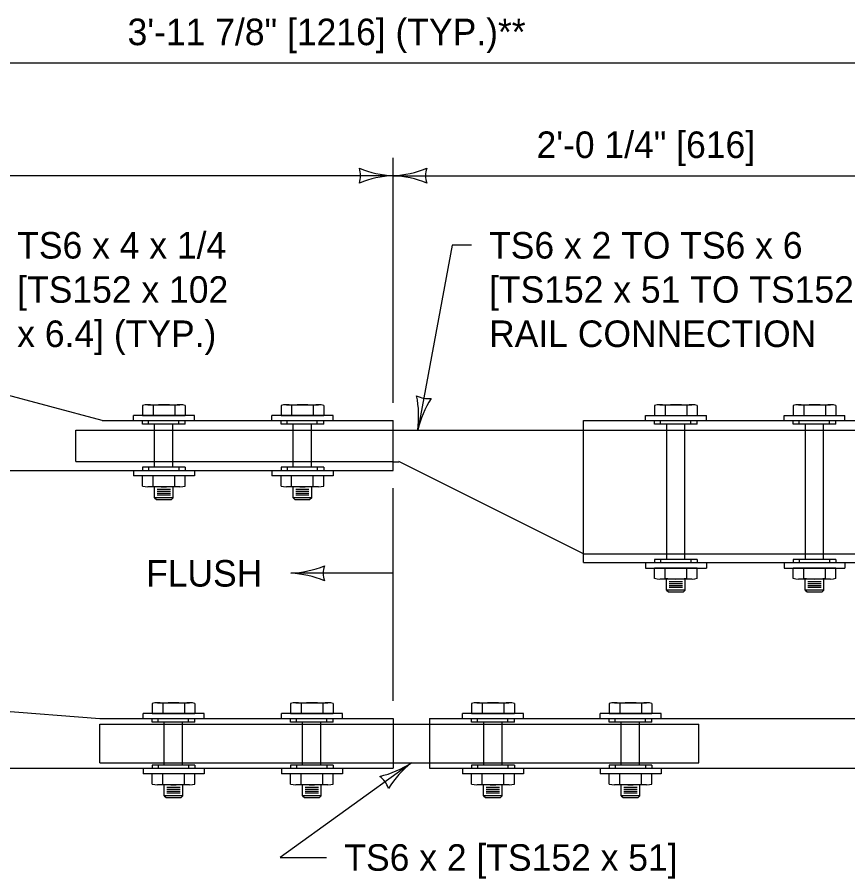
# Model space of a CAD drawing. Extents: x 49991.4 to 50021, y 49987.6 to 50011.4.
# Drawn here: x 50006.762 to 50008.64, y 49992.975 to 49994.923 of the extents above; entities that cross this region are included whole.
import ezdxf

# ---------------------------------------------------------------- set-up
doc = ezdxf.new("R2010")
doc.units = 0
for name, color, linetype in [('Level 1', 7, 'Continuous'), ('Level 2', 7, 'Continuous'), ('Level 3', 7, 'Continuous'), ('Level 4', 7, 'Continuous')]:
    doc.layers.add(name, color=color, linetype=linetype)

msp = doc.modelspace()

# ---------------------------------------------------------------- linework, layer by layer
at = {"layer": 'Level 1'}
for p, q in [((50006.954, 49994.0107), (50006.608, 49994.1035)), ((50007.0451, 49994.0451), (50007.0451, 49994.022)), ((50007.0572, 49994.0466), (50007.1295, 49994.0466)), ((50007.069, 49994.0451), (50007.069, 49994.0221)), ((50007.1178, 49994.0451), (50007.1178, 49994.0221)), ((50007.1417, 49994.0451), (50007.1417, 49994.022)), ((50007.3583, 49994.0451), (50007.3583, 49994.022)), ((50007.3704, 49994.0466), (50007.4427, 49994.0466)), ((50007.3822, 49994.0451), (50007.3822, 49994.0221)), ((50007.431, 49994.0451), (50007.431, 49994.0221)), ((50007.4549, 49994.0451), (50007.4549, 49994.022)), ((50008.2031, 49994.0453), (50008.2031, 49994.0222)), ((50008.2152, 49994.0468), (50008.2875, 49994.0468)), ((50008.227, 49994.0453), (50008.227, 49994.0223)), ((50008.2758, 49994.0453), (50008.2758, 49994.0223)), ((50008.2997, 49994.0453), (50008.2997, 49994.0222)), ((50008.5167, 49994.0453), (50008.5167, 49994.0222)), ((50008.5288, 49994.0468), (50008.6011, 49994.0468)), ((50008.5406, 49994.0453), (50008.5406, 49994.0223)), ((50008.5894, 49994.0453), (50008.5894, 49994.0223)), ((50008.6133, 49994.0453), (50008.6133, 49994.0222)), ((50007.1627, 49994.022), (50007.0244, 49994.022)), ((50007.0244, 49994.0107), (50007.0244, 49994.022)), ((50007.0451, 49994.022), (50007.1417, 49994.022)), ((50007.1627, 49994.0107), (50007.1627, 49994.022)), ((50007.4759, 49994.022), (50007.3376, 49994.022)), ((50007.3376, 49994.0107), (50007.3376, 49994.022)), ((50007.3583, 49994.022), (50007.4549, 49994.022)), ((50007.4759, 49994.0107), (50007.4759, 49994.022)), ((50008.1824, 49994.0222), (50008.3206, 49994.0222)), ((50008.1824, 49994.0107), (50008.1824, 49994.0222)), ((50008.2031, 49994.0222), (50008.2997, 49994.0222)), ((50008.3206, 49994.0107), (50008.3206, 49994.0222)), ((50008.496, 49994.0222), (50008.6336, 49994.0222)), ((50008.496, 49994.0107), (50008.496, 49994.0222)), ((50008.5158, 49994.0222), (50008.6234, 49994.0222)), ((50008.5167, 49994.0222), (50008.6133, 49994.0222)), ((50008.6336, 49994.0107), (50008.6336, 49994.0222)), ((50006.954, 49994.0107), (50007.6117, 49994.0107)), ((50007.6117, 49993.898), (50007.6117, 49994.0107)), ((50008.0426, 49994.0107), (50009.1126, 49994.0107)), ((50008.0426, 49993.6898), (50008.0426, 49994.0107)), ((50007.6117, 49993.9892), (50008.0426, 49993.9892)), ((50007.6116, 49993.9179), (50007.625, 49993.9179)), ((50008.0426, 49993.7095), (50007.6249, 49993.9181)), ((50006.7232, 49993.898), (50007.6117, 49993.898)), ((50007.0244, 49993.898), (50007.0244, 49993.8858)), ((50007.1627, 49993.8858), (50007.0244, 49993.8858)), ((50007.1417, 49993.8858), (50007.0451, 49993.8858)), ((50007.0451, 49993.8627), (50007.0451, 49993.8858)), ((50007.069, 49993.8627), (50007.069, 49993.8857)), ((50007.1178, 49993.8627), (50007.1178, 49993.8857)), ((50007.1417, 49993.8627), (50007.1417, 49993.8858)), ((50007.1627, 49993.898), (50007.1627, 49993.8858)), ((50007.3376, 49993.898), (50007.3376, 49993.8858)), ((50007.4759, 49993.8858), (50007.3376, 49993.8858)), ((50007.4549, 49993.8858), (50007.3583, 49993.8858)), ((50007.3583, 49993.8627), (50007.3583, 49993.8858)), ((50007.3822, 49993.8627), (50007.3822, 49993.8857)), ((50007.431, 49993.8627), (50007.431, 49993.8857)), ((50007.4549, 49993.8627), (50007.4549, 49993.8858)), ((50007.4759, 49993.898), (50007.4759, 49993.8858)), ((50007.1296, 49993.8612), (50007.0573, 49993.8612)), ((50007.0722, 49993.8363), (50007.0722, 49993.8613)), ((50007.0783, 49993.8554), (50007.108, 49993.8554)), ((50007.0783, 49993.8512), (50007.108, 49993.8512)), ((50007.0783, 49993.8469), (50007.108, 49993.8469)), ((50007.1144, 49993.8363), (50007.1144, 49993.8613)), ((50007.4428, 49993.8612), (50007.3705, 49993.8612)), ((50007.3854, 49993.8363), (50007.3854, 49993.8613)), ((50007.3915, 49993.8554), (50007.4212, 49993.8554)), ((50007.3915, 49993.8512), (50007.4212, 49993.8512)), ((50007.3915, 49993.8469), (50007.4212, 49993.8469)), ((50007.4276, 49993.8363), (50007.4276, 49993.8613)), ((50007.1144, 49993.8363), (50007.0722, 49993.8363)), ((50007.0722, 49993.8363), (50007.0764, 49993.8321)), ((50007.0764, 49993.8321), (50007.1102, 49993.8321)), ((50007.0783, 49993.8427), (50007.108, 49993.8427)), ((50007.1144, 49993.8363), (50007.1102, 49993.8321)), ((50007.4276, 49993.8363), (50007.3854, 49993.8363)), ((50007.3854, 49993.8363), (50007.3896, 49993.8321)), ((50007.3896, 49993.8321), (50007.4234, 49993.8321)), ((50007.3915, 49993.8427), (50007.4212, 49993.8427)), ((50007.4276, 49993.8363), (50007.4234, 49993.8321)), ((50008.0426, 49993.6898), (50009.0361, 49993.6898)), ((50008.1824, 49993.6898), (50008.1824, 49993.6772)), ((50008.3206, 49993.6898), (50008.3206, 49993.6772)), ((50008.496, 49993.6898), (50008.496, 49993.6772)), ((50008.6336, 49993.6898), (50008.6336, 49993.6772)), ((50008.1824, 49993.6772), (50008.3206, 49993.6772)), ((50008.2997, 49993.6772), (50008.2031, 49993.6772)), ((50008.2031, 49993.6541), (50008.2031, 49993.6772)), ((50008.227, 49993.6541), (50008.227, 49993.6771)), ((50008.2758, 49993.6541), (50008.2758, 49993.6771)), ((50008.2997, 49993.6541), (50008.2997, 49993.6772)), ((50008.496, 49993.6772), (50008.6336, 49993.6772)), ((50008.5158, 49993.6772), (50008.6234, 49993.6772)), ((50008.6133, 49993.6772), (50008.5167, 49993.6772)), ((50008.5167, 49993.6541), (50008.5167, 49993.6772)), ((50008.5406, 49993.6541), (50008.5406, 49993.6771)), ((50008.5894, 49993.6541), (50008.5894, 49993.6771)), ((50008.6133, 49993.6541), (50008.6133, 49993.6772)), ((50008.2876, 49993.6526), (50008.2153, 49993.6526)), ((50008.2302, 49993.6277), (50008.2302, 49993.6527)), ((50008.2724, 49993.6277), (50008.2724, 49993.6527)), ((50008.6012, 49993.6526), (50008.5289, 49993.6526)), ((50008.5438, 49993.6277), (50008.5438, 49993.6527)), ((50008.586, 49993.6277), (50008.586, 49993.6527)), ((50008.2363, 49993.6468), (50008.266, 49993.6468)), ((50008.2363, 49993.6426), (50008.266, 49993.6426)), ((50008.2363, 49993.6383), (50008.266, 49993.6383)), ((50008.2363, 49993.6341), (50008.266, 49993.6341)), ((50008.5499, 49993.6468), (50008.5796, 49993.6468)), ((50008.5499, 49993.6426), (50008.5796, 49993.6426)), ((50008.5499, 49993.6383), (50008.5796, 49993.6383)), ((50008.5499, 49993.6341), (50008.5796, 49993.6341)), ((50008.2724, 49993.6277), (50008.2302, 49993.6277)), ((50008.2302, 49993.6277), (50008.2344, 49993.6235)), ((50008.2344, 49993.6235), (50008.2682, 49993.6235)), ((50008.2724, 49993.6277), (50008.2682, 49993.6235)), ((50008.586, 49993.6277), (50008.5438, 49993.6277)), ((50008.5438, 49993.6277), (50008.548, 49993.6235)), ((50008.548, 49993.6235), (50008.5818, 49993.6235)), ((50008.586, 49993.6277), (50008.5818, 49993.6235)), ((50006.5485, 49993.3681), (50006.9485, 49993.3369)), ((50007.0669, 49993.3713), (50007.0669, 49993.3482)), ((50007.079, 49993.3728), (50007.1513, 49993.3728)), ((50007.0908, 49993.3713), (50007.0908, 49993.3483)), ((50007.1396, 49993.3713), (50007.1396, 49993.3483)), ((50007.1635, 49993.3713), (50007.1635, 49993.3482)), ((50007.3798, 49993.3713), (50007.3798, 49993.3482)), ((50007.3919, 49993.3728), (50007.4642, 49993.3728)), ((50007.4037, 49993.3713), (50007.4037, 49993.3483)), ((50007.4525, 49993.3713), (50007.4525, 49993.3483)), ((50007.4764, 49993.3713), (50007.4764, 49993.3482)), ((50007.7893, 49993.3713), (50007.7893, 49993.3482)), ((50007.8014, 49993.3728), (50007.8737, 49993.3728)), ((50007.8132, 49993.3713), (50007.8132, 49993.3483)), ((50007.862, 49993.3713), (50007.862, 49993.3483)), ((50007.8859, 49993.3713), (50007.8859, 49993.3482)), ((50008.1005, 49993.3713), (50008.1005, 49993.3482)), ((50008.1126, 49993.3728), (50008.1849, 49993.3728)), ((50008.1244, 49993.3713), (50008.1244, 49993.3483)), ((50008.1732, 49993.3713), (50008.1732, 49993.3483)), ((50008.1971, 49993.3713), (50008.1971, 49993.3482)), ((50007.1845, 49993.3482), (50007.0462, 49993.3482)), ((50007.0462, 49993.3369), (50007.0462, 49993.3482)), ((50007.0669, 49993.3482), (50007.1635, 49993.3482)), ((50007.1845, 49993.3369), (50007.1845, 49993.3482)), ((50007.4974, 49993.3482), (50007.3591, 49993.3482)), ((50007.3591, 49993.3369), (50007.3591, 49993.3482)), ((50007.3798, 49993.3482), (50007.4764, 49993.3482)), ((50007.4974, 49993.3369), (50007.4974, 49993.3482)), ((50007.9069, 49993.3482), (50007.7686, 49993.3482)), ((50007.7686, 49993.3369), (50007.7686, 49993.3482)), ((50007.7893, 49993.3482), (50007.8859, 49993.3482)), ((50007.9069, 49993.3369), (50007.9069, 49993.3482)), ((50008.2181, 49993.3482), (50008.0798, 49993.3482)), ((50008.0798, 49993.3369), (50008.0798, 49993.3482)), ((50008.1005, 49993.3482), (50008.1971, 49993.3482)), ((50008.2181, 49993.3369), (50008.2181, 49993.3482)), ((50006.9485, 49993.3369), (50007.6118, 49993.3369)), ((50007.6118, 49993.3369), (50007.6118, 49993.2246)), ((50007.6118, 49993.3244), (50007.6939, 49993.3244)), ((50007.6939, 49993.3369), (50008.7782, 49993.3369)), ((50007.6939, 49993.3369), (50007.6939, 49993.2246)), ((50005.3414, 49993.2246), (50007.6118, 49993.2246)), ((50007.0462, 49993.2246), (50007.0462, 49993.212)), ((50007.1845, 49993.2246), (50007.1845, 49993.212)), ((50007.3591, 49993.2246), (50007.3591, 49993.212)), ((50007.4974, 49993.2246), (50007.4974, 49993.212)), ((50007.6118, 49993.2372), (50007.6939, 49993.2372)), ((50007.6939, 49993.2246), (50008.7782, 49993.2246)), ((50007.7686, 49993.2246), (50007.7686, 49993.212)), ((50007.9069, 49993.2246), (50007.9069, 49993.212)), ((50008.0798, 49993.2246), (50008.0798, 49993.212)), ((50008.2181, 49993.2246), (50008.2181, 49993.212)), ((50007.1845, 49993.212), (50007.0462, 49993.212)), ((50007.1635, 49993.212), (50007.0669, 49993.212)), ((50007.0669, 49993.1889), (50007.0669, 49993.212)), ((50007.0908, 49993.1889), (50007.0908, 49993.2119)), ((50007.1396, 49993.1889), (50007.1396, 49993.2119)), ((50007.1635, 49993.1889), (50007.1635, 49993.212)), ((50007.4974, 49993.212), (50007.3591, 49993.212)), ((50007.4764, 49993.212), (50007.3798, 49993.212)), ((50007.3798, 49993.1889), (50007.3798, 49993.212)), ((50007.4037, 49993.1889), (50007.4037, 49993.2119)), ((50007.4525, 49993.1889), (50007.4525, 49993.2119)), ((50007.4764, 49993.1889), (50007.4764, 49993.212)), ((50007.9069, 49993.212), (50007.7686, 49993.212)), ((50007.8859, 49993.212), (50007.7893, 49993.212)), ((50007.7893, 49993.1889), (50007.7893, 49993.212)), ((50007.8132, 49993.1889), (50007.8132, 49993.2119)), ((50007.862, 49993.1889), (50007.862, 49993.2119)), ((50007.8859, 49993.1889), (50007.8859, 49993.212)), ((50008.2181, 49993.212), (50008.0798, 49993.212)), ((50008.1971, 49993.212), (50008.1005, 49993.212)), ((50008.1005, 49993.1889), (50008.1005, 49993.212)), ((50008.1244, 49993.1889), (50008.1244, 49993.2119)), ((50008.1732, 49993.1889), (50008.1732, 49993.2119)), ((50008.1971, 49993.1889), (50008.1971, 49993.212)), ((50007.1514, 49993.1874), (50007.0791, 49993.1874)), ((50007.094, 49993.1625), (50007.094, 49993.1875)), ((50007.1362, 49993.1625), (50007.1362, 49993.1875)), ((50007.4643, 49993.1874), (50007.392, 49993.1874)), ((50007.4069, 49993.1625), (50007.4069, 49993.1875)), ((50007.4491, 49993.1625), (50007.4491, 49993.1875)), ((50007.8738, 49993.1874), (50007.8015, 49993.1874)), ((50007.8164, 49993.1625), (50007.8164, 49993.1875)), ((50007.8586, 49993.1625), (50007.8586, 49993.1875)), ((50008.185, 49993.1874), (50008.1127, 49993.1874)), ((50008.1276, 49993.1625), (50008.1276, 49993.1875)), ((50008.1698, 49993.1625), (50008.1698, 49993.1875)), ((50007.1001, 49993.1816), (50007.1298, 49993.1816)), ((50007.1001, 49993.1774), (50007.1298, 49993.1774)), ((50007.1001, 49993.1731), (50007.1298, 49993.1731)), ((50007.1001, 49993.1689), (50007.1298, 49993.1689)), ((50007.413, 49993.1816), (50007.4427, 49993.1816)), ((50007.413, 49993.1774), (50007.4427, 49993.1774)), ((50007.413, 49993.1731), (50007.4427, 49993.1731)), ((50007.413, 49993.1689), (50007.4427, 49993.1689)), ((50007.8225, 49993.1816), (50007.8522, 49993.1816)), ((50007.8225, 49993.1774), (50007.8522, 49993.1774)), ((50007.8225, 49993.1731), (50007.8522, 49993.1731)), ((50007.8225, 49993.1689), (50007.8522, 49993.1689)), ((50008.1337, 49993.1816), (50008.1634, 49993.1816)), ((50008.1337, 49993.1774), (50008.1634, 49993.1774)), ((50008.1337, 49993.1731), (50008.1634, 49993.1731)), ((50008.1337, 49993.1689), (50008.1634, 49993.1689)), ((50007.1362, 49993.1625), (50007.094, 49993.1625)), ((50007.094, 49993.1625), (50007.0982, 49993.1583)), ((50007.0982, 49993.1583), (50007.132, 49993.1583)), ((50007.1362, 49993.1625), (50007.132, 49993.1583)), ((50007.4491, 49993.1625), (50007.4069, 49993.1625)), ((50007.4069, 49993.1625), (50007.4111, 49993.1583)), ((50007.4111, 49993.1583), (50007.4449, 49993.1583)), ((50007.4491, 49993.1625), (50007.4449, 49993.1583)), ((50007.8586, 49993.1625), (50007.8164, 49993.1625)), ((50007.8164, 49993.1625), (50007.8206, 49993.1583)), ((50007.8206, 49993.1583), (50007.8544, 49993.1583)), ((50007.8586, 49993.1625), (50007.8544, 49993.1583)), ((50008.1698, 49993.1625), (50008.1276, 49993.1625)), ((50008.1276, 49993.1625), (50008.1318, 49993.1583)), ((50008.1318, 49993.1583), (50008.1656, 49993.1583)), ((50008.1698, 49993.1625), (50008.1656, 49993.1583))]:
    msp.add_line(p, q, dxfattribs=at)
for centre, major_axis, start_param, end_param in [((50007.0572, 49994.0349), (0.0242, 0), 1.056847, 2.094396), ((50007.0934, 49993.9999), (0.0966, 0), 1.315951, 1.825641), ((50007.1296, 49994.0349), (0.0242, 0), 1.047198, 2.084746), ((50007.3704, 49994.0349), (0.0242, 0), 1.056847, 2.094396), ((50007.4066, 49993.9999), (0.0966, 0), 1.315951, 1.825641), ((50007.4428, 49994.0349), (0.0242, 0), 1.047198, 2.084746), ((50008.2152, 49994.0351), (0.0242, 0), 1.056847, 2.094396), ((50008.2514, 49994.0001), (0.0966, 0), 1.315951, 1.825641), ((50008.2876, 49994.0351), (0.0242, 0), 1.047198, 2.084746), ((50008.5288, 49994.0351), (0.0242, 0), 1.056847, 2.094396), ((50008.565, 49994.0001), (0.0966, 0), 1.315951, 1.825641), ((50008.6012, 49994.0351), (0.0242, 0), 1.047198, 2.084746), ((50007.0572, 49993.8729), (-0.0242, 0), 1.047198, 2.084746), ((50007.0934, 49993.9079), (-0.0966, 0), 1.315951, 1.825641), ((50007.1296, 49993.8729), (-0.0242, 0), 1.056847, 2.094396), ((50007.3704, 49993.8729), (-0.0242, 0), 1.047198, 2.084746), ((50007.4066, 49993.9079), (-0.0966, 0), 1.315951, 1.825641), ((50007.4428, 49993.8729), (-0.0242, 0), 1.056847, 2.094396), ((50008.2152, 49993.6643), (-0.0242, 0), 1.047198, 2.084746), ((50008.2514, 49993.6993), (-0.0966, 0), 1.315951, 1.825641), ((50008.2876, 49993.6643), (-0.0242, 0), 1.056847, 2.094396), ((50008.5288, 49993.6643), (-0.0242, 0), 1.047198, 2.084746), ((50008.565, 49993.6993), (-0.0966, 0), 1.315951, 1.825641), ((50008.6012, 49993.6643), (-0.0242, 0), 1.056847, 2.094396), ((50007.079, 49993.3611), (0.0242, 0), 1.056847, 2.094396), ((50007.1152, 49993.3261), (0.0966, 0), 1.315951, 1.825641), ((50007.1514, 49993.3611), (0.0242, 0), 1.047198, 2.084746), ((50007.3919, 49993.3611), (0.0242, 0), 1.056847, 2.094396), ((50007.4281, 49993.3261), (0.0966, 0), 1.315951, 1.825641), ((50007.4643, 49993.3611), (0.0242, 0), 1.047198, 2.084746), ((50007.8014, 49993.3611), (0.0242, 0), 1.056847, 2.094396), ((50007.8376, 49993.3261), (0.0966, 0), 1.315951, 1.825641), ((50007.8738, 49993.3611), (0.0242, 0), 1.047198, 2.084746), ((50008.1126, 49993.3611), (0.0242, 0), 1.056847, 2.094396), ((50008.1488, 49993.3261), (0.0966, 0), 1.315951, 1.825641), ((50008.185, 49993.3611), (0.0242, 0), 1.047198, 2.084746), ((50007.079, 49993.1991), (-0.0242, 0), 1.047198, 2.084746), ((50007.1152, 49993.2341), (-0.0966, 0), 1.315951, 1.825641), ((50007.1514, 49993.1991), (-0.0242, 0), 1.056847, 2.094396), ((50007.3919, 49993.1991), (-0.0242, 0), 1.047198, 2.084746), ((50007.4281, 49993.2341), (-0.0966, 0), 1.315951, 1.825641), ((50007.4643, 49993.1991), (-0.0242, 0), 1.056847, 2.094396), ((50007.8014, 49993.1991), (-0.0242, 0), 1.047198, 2.084746), ((50007.8376, 49993.2341), (-0.0966, 0), 1.315951, 1.825641), ((50007.8738, 49993.1991), (-0.0242, 0), 1.056847, 2.094396), ((50008.1126, 49993.1991), (-0.0242, 0), 1.047198, 2.084746), ((50008.1488, 49993.2341), (-0.0966, 0), 1.315951, 1.825641), ((50008.185, 49993.1991), (-0.0242, 0), 1.056847, 2.094396)]:
    msp.add_ellipse(centre, major_axis=major_axis, ratio=0.483301, start_param=start_param, end_param=end_param, dxfattribs=at)
at = {"layer": 'Level 3'}
for p, q in [((50006.3999, 49994.8197), (50008.9351, 49994.8197)), ((50007.6116, 49994.0507), (50007.6116, 49994.6046)), ((50007.6116, 49994.5646), (50005.3414, 49994.5646)), ((50007.6116, 49994.5646), (50008.9351, 49994.5646)), ((50007.7454, 49994.4072), (50007.6674, 49993.9892)), ((50007.7887, 49994.4072), (50007.7454, 49994.4072)), ((50007.6119, 49993.3769), (50007.6119, 49993.858)), ((50007.6119, 49993.6655), (50007.3802, 49993.6655)), ((50007.653, 49993.2372), (50007.356, 49993.0229)), ((50007.356, 49993.0229), (50007.4614, 49993.0229))]:
    msp.add_line(p, q, dxfattribs=at)
for centre, radius, start, end in [((50007.6208, 49994.7867), 0.2223, 247.456, 267.6395), ((50007.4834, 49994.5646), 0.0548, 342.1388, 17.8612), ((50007.6001, 49994.7973), 0.233, 272.8273, 292.0772), ((50007.7398, 49994.5646), 0.0548, 162.1388, 197.8612), ((50007.6231, 49994.3319), 0.233, 92.8273, 112.0772), ((50007.6025, 49994.3425), 0.2223, 67.456, 87.6395), ((50007.6909, 49994.1152), 0.0548, 241.5671, 277.2895), ((50007.4365, 49994.0206), 0.233, 352.2556, 11.5055), ((50007.8841, 49993.9394), 0.2223, 146.8843, 167.0678), ((50007.3687, 49993.8983), 0.233, 272.8273, 292.0772), ((50007.5084, 49993.6655), 0.0548, 162.1388, 197.8612), ((50007.3711, 49993.4434), 0.2223, 67.456, 87.6395), ((50007.5305, 49993.4227), 0.2223, 283.2637, 303.4472), ((50007.7985, 49993.0552), 0.233, 128.635, 147.8848), ((50007.549, 49993.1622), 0.0548, 17.9465, 53.6688)]:
    msp.add_arc(centre, radius, start, end, dxfattribs=at)
at = {"layer": 'Level 4'}
for p, q in [((50007.0451, 49994.0028), (50007.0451, 49994.0107)), ((50007.1417, 49994.0028), (50007.0451, 49994.0028)), ((50007.0587, 49994.0028), (50007.0587, 49994.0107)), ((50007.0724, 49993.9056), (50007.0724, 49994.0028)), ((50007.1138, 49993.9056), (50007.1138, 49994.0028)), ((50007.1271, 49994.0028), (50007.1271, 49994.0107)), ((50007.1417, 49994.0028), (50007.1417, 49994.0107)), ((50007.3583, 49994.0028), (50007.3583, 49994.0107)), ((50007.4549, 49994.0028), (50007.3583, 49994.0028)), ((50007.3719, 49994.0028), (50007.3719, 49994.0107)), ((50007.3856, 49993.9056), (50007.3856, 49994.0028)), ((50007.427, 49993.9056), (50007.427, 49994.0028)), ((50007.4403, 49994.0028), (50007.4403, 49994.0107)), ((50007.4549, 49994.0028), (50007.4549, 49994.0107)), ((50008.2031, 49994.003), (50008.2031, 49994.0107)), ((50008.2997, 49994.003), (50008.2031, 49994.003)), ((50008.2167, 49994.003), (50008.2167, 49994.0107)), ((50008.2304, 49993.697), (50008.2304, 49994.003)), ((50008.2718, 49993.697), (50008.2718, 49994.003)), ((50008.2851, 49994.003), (50008.2851, 49994.0107)), ((50008.2997, 49994.003), (50008.2997, 49994.0107)), ((50008.5167, 49994.003), (50008.5167, 49994.0107)), ((50008.6133, 49994.003), (50008.5167, 49994.003)), ((50008.5303, 49994.003), (50008.5303, 49994.0107)), ((50008.544, 49993.697), (50008.544, 49994.003)), ((50008.5854, 49993.697), (50008.5854, 49994.003)), ((50008.5987, 49994.003), (50008.5987, 49994.0107)), ((50008.6133, 49994.003), (50008.6133, 49994.0107)), ((50006.8942, 49993.9892), (50007.6117, 49993.9892)), ((50006.8942, 49993.9181), (50006.8942, 49993.9892)), ((50008.0426, 49993.9892), (50008.7737, 49993.9892)), ((50006.8942, 49993.9181), (50007.6117, 49993.9181)), ((50007.1417, 49993.9056), (50007.0451, 49993.9056)), ((50007.0451, 49993.9056), (50007.0451, 49993.898)), ((50007.0587, 49993.9056), (50007.0587, 49993.898)), ((50007.1271, 49993.9056), (50007.1271, 49993.898)), ((50007.1417, 49993.9056), (50007.1417, 49993.898)), ((50007.4549, 49993.9056), (50007.3583, 49993.9056)), ((50007.3583, 49993.9056), (50007.3583, 49993.898)), ((50007.3719, 49993.9056), (50007.3719, 49993.898)), ((50007.4403, 49993.9056), (50007.4403, 49993.8984)), ((50007.4549, 49993.9056), (50007.4549, 49993.8984)), ((50008.0426, 49993.7095), (50008.7737, 49993.7095)), ((50008.2997, 49993.697), (50008.2031, 49993.697)), ((50008.2031, 49993.697), (50008.2031, 49993.6898)), ((50008.2167, 49993.697), (50008.2167, 49993.6898)), ((50008.2851, 49993.697), (50008.2851, 49993.6898)), ((50008.2997, 49993.697), (50008.2997, 49993.6898)), ((50008.6133, 49993.697), (50008.5167, 49993.697)), ((50008.5167, 49993.697), (50008.5167, 49993.6898)), ((50008.5303, 49993.697), (50008.5303, 49993.6898)), ((50008.5987, 49993.697), (50008.5987, 49993.6898)), ((50008.6133, 49993.697), (50008.6133, 49993.6898)), ((50006.9485, 49993.3244), (50007.6118, 49993.3244)), ((50006.9485, 49993.2372), (50006.9485, 49993.3244)), ((50007.0669, 49993.329), (50007.0669, 49993.3369)), ((50007.1635, 49993.329), (50007.0669, 49993.329)), ((50007.0805, 49993.329), (50007.0805, 49993.3369)), ((50007.0942, 49993.2318), (50007.0942, 49993.329)), ((50007.1356, 49993.2318), (50007.1356, 49993.329)), ((50007.1489, 49993.329), (50007.1489, 49993.3369)), ((50007.1635, 49993.329), (50007.1635, 49993.3369)), ((50007.3798, 49993.329), (50007.3798, 49993.3369)), ((50007.4764, 49993.329), (50007.3798, 49993.329)), ((50007.3934, 49993.329), (50007.3934, 49993.3369)), ((50007.4071, 49993.2318), (50007.4071, 49993.329)), ((50007.4485, 49993.2318), (50007.4485, 49993.329)), ((50007.4618, 49993.329), (50007.4618, 49993.3369)), ((50007.4764, 49993.329), (50007.4764, 49993.3369)), ((50007.6939, 49993.3244), (50008.3029, 49993.3244)), ((50007.7893, 49993.329), (50007.7893, 49993.3369)), ((50007.8859, 49993.329), (50007.7893, 49993.329)), ((50007.8029, 49993.329), (50007.8029, 49993.3369)), ((50007.8166, 49993.2318), (50007.8166, 49993.329)), ((50007.858, 49993.2318), (50007.858, 49993.329)), ((50007.8713, 49993.329), (50007.8713, 49993.3369)), ((50007.8859, 49993.329), (50007.8859, 49993.3369)), ((50008.1005, 49993.329), (50008.1005, 49993.3369)), ((50008.1971, 49993.329), (50008.1005, 49993.329)), ((50008.1141, 49993.329), (50008.1141, 49993.3369)), ((50008.1278, 49993.2318), (50008.1278, 49993.329)), ((50008.1692, 49993.2318), (50008.1692, 49993.329)), ((50008.1825, 49993.329), (50008.1825, 49993.3369)), ((50008.1971, 49993.329), (50008.1971, 49993.3369)), ((50008.3029, 49993.2372), (50008.3029, 49993.3244)), ((50006.9485, 49993.2372), (50007.6118, 49993.2372)), ((50007.1635, 49993.2318), (50007.0669, 49993.2318)), ((50007.0669, 49993.2318), (50007.0669, 49993.2246)), ((50007.0805, 49993.2318), (50007.0805, 49993.2246)), ((50007.1489, 49993.2318), (50007.1489, 49993.2246)), ((50007.1635, 49993.2318), (50007.1635, 49993.2246)), ((50007.4764, 49993.2318), (50007.3798, 49993.2318)), ((50007.3798, 49993.2318), (50007.3798, 49993.2246)), ((50007.3934, 49993.2318), (50007.3934, 49993.2246)), ((50007.4618, 49993.2318), (50007.4618, 49993.2246)), ((50007.4764, 49993.2318), (50007.4764, 49993.2246)), ((50007.6939, 49993.2372), (50008.3029, 49993.2372)), ((50007.8859, 49993.2318), (50007.7893, 49993.2318)), ((50007.7893, 49993.2318), (50007.7893, 49993.2246)), ((50007.8029, 49993.2318), (50007.8029, 49993.2246)), ((50007.8713, 49993.2318), (50007.8713, 49993.2246)), ((50007.8859, 49993.2318), (50007.8859, 49993.2246)), ((50008.1971, 49993.2318), (50008.1005, 49993.2318)), ((50008.1005, 49993.2318), (50008.1005, 49993.2246)), ((50008.1141, 49993.2318), (50008.1141, 49993.2246)), ((50008.1825, 49993.2318), (50008.1825, 49993.2246)), ((50008.1971, 49993.2318), (50008.1971, 49993.2246))]:
    msp.add_line(p, q, dxfattribs=at)

# ---------------------------------------------------------------- texts
at = {"layer": 'Level 2'}
for s, p in [('3\'-11 7/8" [1216] (TYP.)**', (50007.0112, 49994.8597)), ('2\'-0 1/4" [616]', (50007.9361, 49994.6046)), ('TS6 x 4 x 1/4', (50006.7616, 49994.3772)), ('TS6 x 2 TO TS6 x 6 ', (50007.8287, 49994.3772)), ('[TS152 x 102', (50006.7616, 49994.2772)), ('[TS152 x 51 TO TS152 x 152]', (50007.8287, 49994.2772)), ('x 6.4] (TYP.)', (50006.7616, 49994.1772)), ('RAIL CONNECTION', (50007.8287, 49994.1772)), ('FLUSH', (50007.0529, 49993.6355)), ('TS6 x 2 [TS152 x 51]', (50007.5014, 49992.9929))]:
    msp.add_text(s, height=0.06, dxfattribs=at).set_placement(p)

doc.saveas('drawing.dxf')
